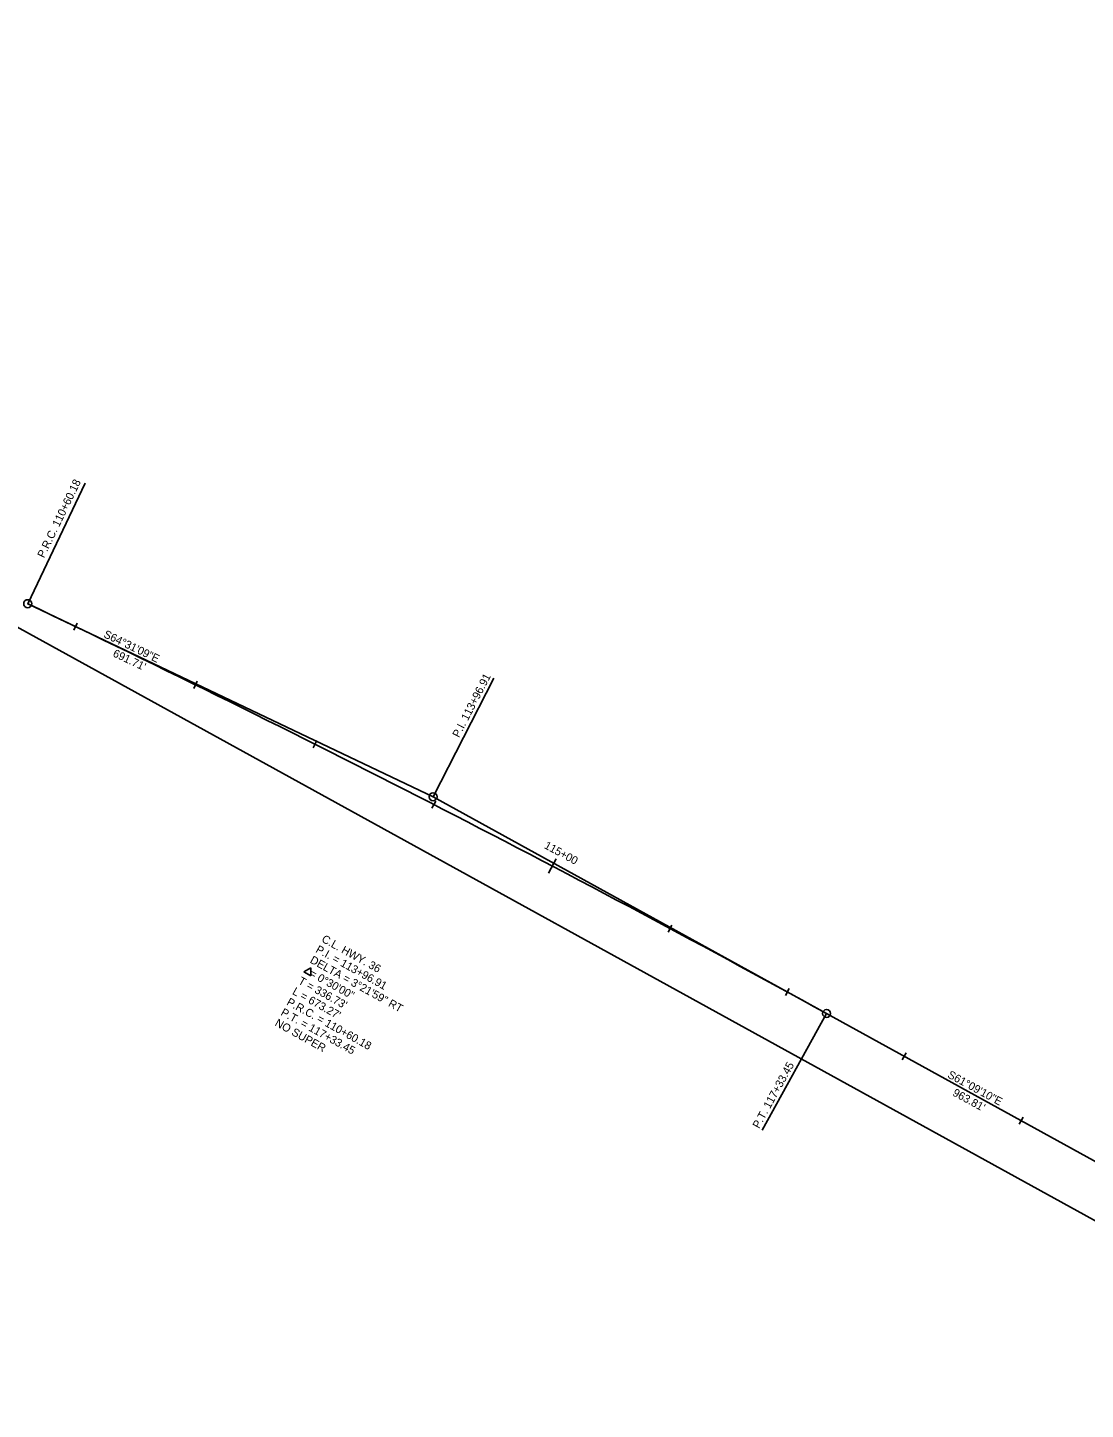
# Model space of a CAD drawing. Extents: x 1451272 to 1457767, y 301145 to 304591.
# Drawn here: x 1454102 to 1454895, y 302567 to 303603 of the extents above; entities that cross this region are included whole.
import ezdxf

# ---------------------------------------------------------------- set-up
doc = ezdxf.new("R2010")
doc.units = 0
for name, color, linetype in [('CL_Highway_1', 7, 'Continuous'), ('CL_Highway_1_text', 7, 'Continuous'), ('CL_Tangent', 7, 'Continuous'), ('CL_Tangent_Length', 7, 'Continuous'), ('CurveData_100', 7, 'Continuous'), ('PCPT_100_CL_ALT1', 7, 'Continuous'), ('PCPT_100_CL_Annot', 7, 'Continuous'), ('PI_100_CL_ALT1', 7, 'Continuous'), ('PI_100_CL_Annot', 7, 'Continuous'), ('Point_CL_Highway_2', 7, 'Continuous'), ('RD_Exist_CL', 7, 'Continuous'), ('STA_100_CL', 7, 'Continuous'), ('TICK_100_CL', 7, 'Continuous')]:
    doc.layers.add(name, color=color, linetype=linetype)

msp = doc.modelspace()

# ---------------------------------------------------------------- linework, layer by layer
at = {"layer": 'CL_Highway_1'}
msp.add_line((1454700.9, 302864.2), (1454970.6, 302715.7), dxfattribs=at)
msp.add_line((1454700.9, 302864.2), (1454970.6, 302715.7), dxfattribs=at)
msp.add_line((1454700.9, 302864.2), (1454970.6, 302715.7), dxfattribs=at)
msp.add_line((1454700.9, 302864.2), (1454970.6, 302715.7), dxfattribs=at)
msp.add_line((1454700.9, 302864.2), (1454970.6, 302715.7), dxfattribs=at)
msp.add_line((1454700.9, 302864.2), (1454970.6, 302715.7), dxfattribs=at)
msp.add_line((1454700.9, 302864.2), (1454970.6, 302715.7), dxfattribs=at)
msp.add_arc((1449172.1, 292827), 11459.2, 61.15287, 64.5192, dxfattribs=at)
msp.add_arc((1449172.1, 292827), 11459.2, 61.15287, 64.5192, dxfattribs=at)
msp.add_arc((1449172.1, 292827), 11459.2, 61.15287, 64.5192, dxfattribs=at)
msp.add_arc((1449172.1, 292827), 11459.2, 61.15287, 64.5192, dxfattribs=at)
msp.add_arc((1449172.1, 292827), 11459.2, 61.15287, 64.5192, dxfattribs=at)
msp.add_arc((1449172.1, 292827), 11459.2, 61.15287, 64.5192, dxfattribs=at)
msp.add_arc((1449172.1, 292827), 11459.2, 61.15287, 64.5192, dxfattribs=at)
at = {"layer": 'CL_Tangent'}
for p, q in [((1454102, 303171.5), (1454405.9, 303026.7)), ((1454405.9, 303026.7), (1454700.9, 302864.2))]:
    msp.add_line(p, q, dxfattribs=at)
for centre in [(1454102, 303171.5), (1454405.9, 303026.7), (1454700.9, 302864.2)]:
    msp.add_circle(centre, 3, dxfattribs=at)
at = {"layer": 'CurveData_100'}
for p, q in [((1454314.2, 302898.5), (1454309, 302895.4)), ((1454309, 302895.4), (1454314.3, 302892.5)), ((1454314.2, 302898.5), (1454314.3, 302892.5))]:
    msp.add_line(p, q, dxfattribs=at)
at = {"layer": 'PCPT_100_CL_ALT1'}
for points in [[(1454102, 303171.5), (1454145, 303261.8)], [(1454700.9, 302864.2), (1454652.6, 302776.6)]]:
    msp.add_lwpolyline(points, dxfattribs=at)
at = {"layer": 'PI_100_CL_ALT1'}
msp.add_lwpolyline([(1454405.9, 303026.7), (1454451.6, 303115.6)], dxfattribs=at)
at = {"layer": 'Point_CL_Highway_2'}
for centre in [(1454102, 303171.5), (1454102, 303171.5), (1454102, 303171.5), (1454700.9, 302864.2), (1454700.9, 302864.2)]:
    msp.add_circle(centre, 3, dxfattribs=at)
at = {"layer": 'RD_Exist_CL'}
msp.add_line((1453278, 303603.4), (1455158.9, 302567.4), dxfattribs=at)
at = {"layer": 'TICK_100_CL'}
for points in [[(1454139.2, 303157), (1454136.6, 303151.6)], [(1454229.1, 303113.3), (1454226.5, 303107.9)], [(1454318.7, 303068.8), (1454316, 303063.4)], [(1454407.9, 303023.5), (1454405.1, 303018.1)], [(1454498.1, 302980.1), (1454492.5, 302969.4)], [(1454585, 302930.5), (1454582.2, 302925.3)], [(1454673, 302882.9), (1454670.1, 302877.7)], [(1454760.6, 302834.7), (1454757.7, 302829.5)], [(1454848.2, 302786.5), (1454845.3, 302781.2)]]:
    msp.add_lwpolyline(points, dxfattribs=at)

# ---------------------------------------------------------------- texts
at = {"layer": 'CL_Highway_1_text'}
for s, rotation, p in [('S64%%d31\'09"E', 334.2868, (1454158.4, 303146.6)), ('S61%%d09\'10"E', 331.4111, (1454791.1, 302816.5))]:
    msp.add_text(s, height=6, rotation=rotation, dxfattribs=at).set_placement(p)
at = {"layer": 'CL_Tangent_Length'}
for s, rotation, p in [("691.71'", 334.7804, (1454165.3, 303132.2)), ("963.81'", 331.4111, (1454794.9, 302803))]:
    msp.add_text(s, height=6, rotation=rotation, dxfattribs=at).set_placement(p)
at = {"layer": 'CurveData_100'}
for s, p in [('P.I. = 113+96.91', (1454317.4, 302910.5)), ('C.L. HWY. 36', (1454321.8, 302918.3)), ('DELTA = 3%%d21\'59" RT', (1454313.1, 302902.6)), ('  = 0%%d30\'00"', (1454308.7, 302894.7)), ("L = 673.27'", (1454299.9, 302879)), ("T = 336.73'", (1454304.3, 302886.9)), ('P.R.C. = 110+60.18', (1454295.6, 302871.1)), ('P.T. = 117+33.45', (1454291.2, 302863.3)), ('NO SUPER', (1454286.8, 302855.4))]:
    msp.add_text(s, height=6, rotation=330.951, dxfattribs=at).set_placement(p)
at = {"layer": 'PCPT_100_CL_Annot'}
for s, rotation, p in [('P.R.C. 110+60.18', 64.2601, (1454114.3, 303205.3)), ('P.T. 117+33.45', 61.1975, (1454650.3, 302777.5))]:
    msp.add_text(s, height=6, rotation=rotation, dxfattribs=at).set_placement(p)
at = {"layer": 'PI_100_CL_Annot'}
msp.add_text('P.I. 113+96.91', height=6, rotation=62.6899, dxfattribs=at).set_placement((1454425.4, 303070.6))
at = {"layer": 'STA_100_CL'}
msp.add_text('115+00', height=6, rotation=331.593, dxfattribs=at).set_placement((1454488.7, 302988.4))

doc.saveas('drawing.dxf')
